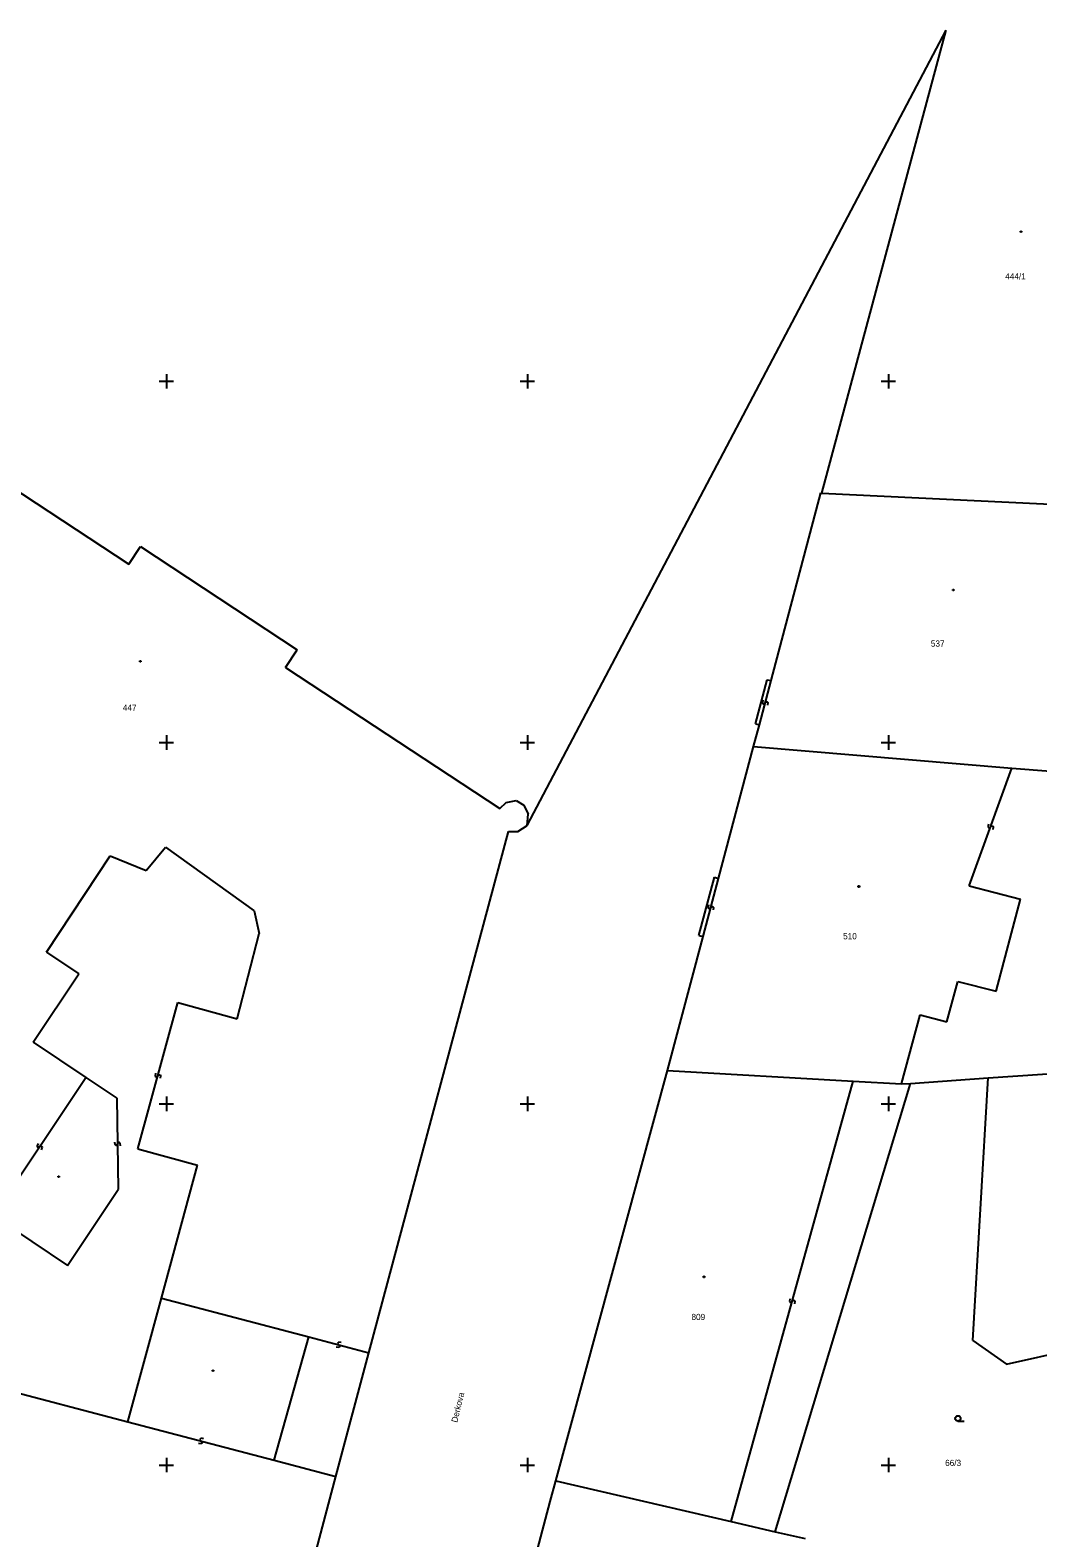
# Model space of a CAD drawing. Extents: x -492811 to -492366, y -1127107 to -1126748.
# Drawn here: x -492547.5 to -492491.7, y -1126844 to -1126760.6 of the extents above; entities that cross this region are included whole.
import ezdxf

# ---------------------------------------------------------------- set-up
doc = ezdxf.new("R2010")
doc.units = 0
doc.layers.add('katastrální mapa', color=7, linetype='Continuous')
doc.layers.add('síť', color=7, linetype='Continuous')

msp = doc.modelspace()

# ---------------------------------------------------------------- linework, layer by layer
at = {"layer": 'katastrální mapa'}
for p, q in [((-492520.02, -1126804.6), (-492496.81, -1126760.56)), ((-492503.68, -1126786.2), (-492496.81, -1126760.56)), ((-492492.68, -1126771.68), (-492492.62, -1126771.68)), ((-492492.68, -1126771.74), (-492492.68, -1126771.68)), ((-492492.62, -1126771.74), (-492492.68, -1126771.74)), ((-492492.62, -1126771.68), (-492492.62, -1126771.74)), ((-492554.24, -1126782.12), (-492542.08, -1126790.12)), ((-492506.5, -1126796.57), (-492503.75, -1126786.18)), ((-492503.75, -1126786.18), (-492503.68, -1126786.2)), ((-492503.68, -1126786.2), (-492489.88, -1126786.86)), ((-492542.08, -1126790.12), (-492541.44, -1126789.14)), ((-492541.44, -1126789.14), (-492532.75, -1126794.86)), ((-492496.43, -1126791.53), (-492496.37, -1126791.53)), ((-492496.43, -1126791.59), (-492496.43, -1126791.53)), ((-492496.37, -1126791.53), (-492496.37, -1126791.59)), ((-492496.37, -1126791.59), (-492496.43, -1126791.59)), ((-492533.4, -1126795.84), (-492532.75, -1126794.86)), ((-492541.47, -1126795.47), (-492541.41, -1126795.47)), ((-492541.47, -1126795.53), (-492541.47, -1126795.47)), ((-492541.41, -1126795.53), (-492541.47, -1126795.53)), ((-492541.41, -1126795.47), (-492541.41, -1126795.53)), ((-492533.4, -1126795.84), (-492521.53, -1126803.65)), ((-492507.36, -1126798.97), (-492506.71, -1126796.52)), ((-492507.15, -1126799.02), (-492506.5, -1126796.57)), ((-492506.71, -1126796.52), (-492506.5, -1126796.57)), ((-492506.95, -1126797.66), (-492506.97, -1126797.8)), ((-492506.97, -1126797.8), (-492506.94, -1126797.85)), ((-492506.94, -1126797.85), (-492506.9, -1126797.86)), ((-492506.9, -1126797.86), (-492506.85, -1126797.83)), ((-492506.85, -1126797.83), (-492506.8, -1126797.76)), ((-492506.8, -1126797.76), (-492506.75, -1126797.73)), ((-492506.75, -1126797.73), (-492506.71, -1126797.74)), ((-492506.71, -1126797.74), (-492506.68, -1126797.79)), ((-492506.68, -1126797.79), (-492506.7, -1126797.93)), ((-492507.47, -1126800.22), (-492507.15, -1126799.02)), ((-492507.36, -1126798.97), (-492507.15, -1126799.02)), ((-492509.41, -1126807.52), (-492507.47, -1126800.22)), ((-492507.47, -1126800.22), (-492493.16, -1126801.41)), ((-492495.52, -1126807.93), (-492493.16, -1126801.41)), ((-492493.16, -1126801.41), (-492491.03, -1126801.59)), ((-492521.17, -1126803.31), (-492520.62, -1126803.21)), ((-492520.62, -1126803.21), (-492520.2, -1126803.47)), ((-492521.53, -1126803.65), (-492521.17, -1126803.31)), ((-492520.2, -1126803.47), (-492519.95, -1126803.97)), ((-492520.02, -1126804.6), (-492519.95, -1126803.97)), ((-492528.79, -1126833.78), (-492521.05, -1126804.92)), ((-492521.05, -1126804.92), (-492520.53, -1126804.93)), ((-492520.53, -1126804.93), (-492520.02, -1126804.6)), ((-492494.46, -1126804.52), (-492494.49, -1126804.66)), ((-492494.49, -1126804.66), (-492494.46, -1126804.71)), ((-492494.46, -1126804.71), (-492494.42, -1126804.72)), ((-492494.42, -1126804.72), (-492494.37, -1126804.7)), ((-492494.37, -1126804.7), (-492494.31, -1126804.64)), ((-492494.31, -1126804.64), (-492494.26, -1126804.62)), ((-492494.26, -1126804.62), (-492494.22, -1126804.63)), ((-492494.22, -1126804.63), (-492494.19, -1126804.68)), ((-492494.19, -1126804.68), (-492494.22, -1126804.82)), ((-492546.63, -1126811.61), (-492543.11, -1126806.27)), ((-492543.11, -1126806.27), (-492541.12, -1126807.09)), ((-492541.12, -1126807.09), (-492540.04, -1126805.79)), ((-492540.04, -1126805.79), (-492535.14, -1126809.32)), ((-492510.5, -1126810.68), (-492509.64, -1126807.45)), ((-492510.26, -1126810.74), (-492509.41, -1126807.52)), ((-492509.64, -1126807.45), (-492509.41, -1126807.52)), ((-492501.67, -1126807.94), (-492501.61, -1126807.94)), ((-492501.67, -1126808), (-492501.67, -1126807.94)), ((-492501.61, -1126808), (-492501.67, -1126808)), ((-492501.61, -1126807.94), (-492501.61, -1126808)), ((-492495.52, -1126807.93), (-492492.69, -1126808.68)), ((-492509.96, -1126808.99), (-492509.98, -1126809.13)), ((-492509.86, -1126809.16), (-492509.81, -1126809.1)), ((-492509.81, -1126809.1), (-492509.76, -1126809.07)), ((-492509.76, -1126809.07), (-492509.72, -1126809.08)), ((-492509.72, -1126809.08), (-492509.69, -1126809.13)), ((-492494.04, -1126813.77), (-492492.69, -1126808.68)), ((-492535.14, -1126809.32), (-492534.86, -1126810.58)), ((-492509.98, -1126809.13), (-492509.95, -1126809.18)), ((-492509.95, -1126809.18), (-492509.91, -1126809.19)), ((-492509.91, -1126809.19), (-492509.86, -1126809.16)), ((-492509.69, -1126809.13), (-492509.71, -1126809.27)), ((-492536.07, -1126815.29), (-492534.86, -1126810.58)), ((-492512.23, -1126818.16), (-492510.26, -1126810.74)), ((-492510.5, -1126810.68), (-492510.26, -1126810.74)), ((-492546.63, -1126811.61), (-492544.85, -1126812.8)), ((-492547.38, -1126816.59), (-492544.85, -1126812.8)), ((-492496.77, -1126815.47), (-492496.15, -1126813.22)), ((-492496.15, -1126813.22), (-492494.04, -1126813.77)), ((-492541.58, -1126822.5), (-492539.36, -1126814.4)), ((-492539.36, -1126814.4), (-492536.07, -1126815.29)), ((-492499.28, -1126818.9), (-492498.24, -1126815.07)), ((-492498.24, -1126815.07), (-492496.77, -1126815.47)), ((-492547.38, -1126816.59), (-492544.46, -1126818.54)), ((-492518.43, -1126840.88), (-492512.23, -1126818.16)), ((-492512.23, -1126818.16), (-492501.96, -1126818.75)), ((-492494.47, -1126818.57), (-492484.66, -1126817.9)), ((-492549.58, -1126826.2), (-492544.46, -1126818.54)), ((-492544.46, -1126818.54), (-492542.74, -1126819.69)), ((-492540.6, -1126818.31), (-492540.62, -1126818.45)), ((-492540.62, -1126818.45), (-492540.59, -1126818.5)), ((-492540.59, -1126818.5), (-492540.55, -1126818.51)), ((-492540.55, -1126818.51), (-492540.5, -1126818.48)), ((-492540.5, -1126818.48), (-492540.44, -1126818.42)), ((-492540.44, -1126818.42), (-492540.39, -1126818.39)), ((-492540.39, -1126818.39), (-492540.35, -1126818.4)), ((-492540.35, -1126818.4), (-492540.32, -1126818.45)), ((-492540.32, -1126818.45), (-492540.34, -1126818.59)), ((-492508.71, -1126843.12), (-492501.96, -1126818.75)), ((-492506.28, -1126843.69), (-492498.78, -1126818.87)), ((-492501.96, -1126818.75), (-492499.28, -1126818.9)), ((-492499.28, -1126818.9), (-492498.78, -1126818.87)), ((-492498.78, -1126818.87), (-492494.47, -1126818.57)), ((-492495.32, -1126833.11), (-492494.47, -1126818.57)), ((-492542.74, -1126819.69), (-492542.66, -1126824.75)), ((-492547.1, -1126822.2), (-492547.16, -1126822.33)), ((-492547.16, -1126822.33), (-492547.15, -1126822.38)), ((-492547.15, -1126822.38), (-492547.11, -1126822.4)), ((-492547.11, -1126822.4), (-492547.06, -1126822.39)), ((-492547.06, -1126822.39), (-492546.98, -1126822.35)), ((-492546.98, -1126822.35), (-492546.93, -1126822.34)), ((-492546.88, -1126822.41), (-492546.94, -1126822.54)), ((-492546.93, -1126822.34), (-492546.89, -1126822.36)), ((-492546.89, -1126822.36), (-492546.88, -1126822.41)), ((-492542.84, -1126822.26), (-492542.86, -1126822.12)), ((-492542.8, -1126822.3), (-492542.84, -1126822.26)), ((-492542.76, -1126822.3), (-492542.8, -1126822.3)), ((-492542.72, -1126822.26), (-492542.76, -1126822.3)), ((-492542.68, -1126822.18), (-492542.72, -1126822.26)), ((-492542.64, -1126822.14), (-492542.68, -1126822.18)), ((-492542.6, -1126822.14), (-492542.64, -1126822.14)), ((-492542.56, -1126822.18), (-492542.6, -1126822.14)), ((-492542.54, -1126822.32), (-492542.56, -1126822.18)), ((-492541.58, -1126822.5), (-492538.27, -1126823.4)), ((-492546, -1126824), (-492545.94, -1126824)), ((-492546, -1126824.06), (-492546, -1126824)), ((-492545.94, -1126824.06), (-492546, -1126824.06)), ((-492545.94, -1126824), (-492545.94, -1126824.06)), ((-492540.27, -1126830.76), (-492538.27, -1126823.4)), ((-492545.47, -1126828.95), (-492542.66, -1126824.75)), ((-492549.58, -1126826.2), (-492545.47, -1126828.95)), ((-492510.25, -1126829.55), (-492510.19, -1126829.55)), ((-492510.25, -1126829.61), (-492510.25, -1126829.55)), ((-492510.19, -1126829.61), (-492510.25, -1126829.61)), ((-492510.19, -1126829.55), (-492510.19, -1126829.61)), ((-492542.13, -1126837.61), (-492540.27, -1126830.76)), ((-492540.27, -1126830.76), (-492532.11, -1126832.91)), ((-492505.46, -1126830.8), (-492505.48, -1126830.94)), ((-492505.48, -1126830.94), (-492505.45, -1126830.99)), ((-492505.45, -1126830.99), (-492505.41, -1126831)), ((-492505.41, -1126831), (-492505.36, -1126830.97)), ((-492505.36, -1126830.97), (-492505.31, -1126830.9)), ((-492505.31, -1126830.9), (-492505.26, -1126830.87)), ((-492505.26, -1126830.87), (-492505.22, -1126830.88)), ((-492505.22, -1126830.88), (-492505.19, -1126830.93)), ((-492505.19, -1126830.93), (-492505.21, -1126831.07)), ((-492493.46, -1126834.41), (-492482.75, -1126832.01)), ((-492534.03, -1126839.73), (-492532.11, -1126832.91)), ((-492532.11, -1126832.91), (-492528.79, -1126833.78)), ((-492530.5, -1126833.23), (-492530.51, -1126833.27)), ((-492530.51, -1126833.27), (-492530.48, -1126833.32)), ((-492530.45, -1126833.2), (-492530.5, -1126833.23)), ((-492530.31, -1126833.22), (-492530.45, -1126833.2)), ((-492495.32, -1126833.11), (-492493.46, -1126834.41)), ((-492530.61, -1126840.63), (-492528.79, -1126833.78)), ((-492530.45, -1126833.49), (-492530.59, -1126833.47)), ((-492530.48, -1126833.32), (-492530.42, -1126833.37)), ((-492530.4, -1126833.46), (-492530.45, -1126833.49)), ((-492530.42, -1126833.37), (-492530.39, -1126833.42)), ((-492530.39, -1126833.42), (-492530.4, -1126833.46)), ((-492553.93, -1126834.52), (-492542.13, -1126837.61)), ((-492537.45, -1126834.74), (-492537.39, -1126834.74)), ((-492537.45, -1126834.8), (-492537.45, -1126834.74)), ((-492537.39, -1126834.8), (-492537.45, -1126834.8)), ((-492537.39, -1126834.74), (-492537.39, -1126834.8)), ((-492542.13, -1126837.61), (-492534.03, -1126839.73)), ((-492496.15, -1126837.57), (-492495.8, -1126837.57)), ((-492538.08, -1126838.82), (-492538.22, -1126838.8)), ((-492538.13, -1126838.55), (-492538.14, -1126838.59)), ((-492538.14, -1126838.59), (-492538.11, -1126838.64)), ((-492538.08, -1126838.52), (-492538.13, -1126838.55)), ((-492538.11, -1126838.64), (-492538.05, -1126838.7)), ((-492537.94, -1126838.54), (-492538.08, -1126838.52)), ((-492538.03, -1126838.79), (-492538.08, -1126838.82)), ((-492538.05, -1126838.7), (-492538.02, -1126838.75)), ((-492538.02, -1126838.75), (-492538.03, -1126838.79)), ((-492534.03, -1126839.73), (-492530.61, -1126840.63)), ((-492535.01, -1126857.16), (-492530.61, -1126840.63)), ((-492518.73, -1126842.01), (-492518.43, -1126840.88)), ((-492518.43, -1126840.88), (-492508.71, -1126843.12)), ((-492521.03, -1126850.61), (-492518.73, -1126842.01)), ((-492508.71, -1126843.12), (-492506.28, -1126843.69)), ((-492506.28, -1126843.69), (-492504.62, -1126844.07))]:
    msp.add_line(p, q, dxfattribs=at)
msp.add_circle((-492496.15, -1126837.42), 0.15, dxfattribs=at)
at = {"layer": 'síť'}
for p, q in [((-492540, -1126779.6), (-492540, -1126780.4)), ((-492520, -1126779.6), (-492520, -1126780.4)), ((-492500, -1126779.6), (-492500, -1126780.4)), ((-492540.4, -1126780), (-492539.6, -1126780)), ((-492520.4, -1126780), (-492519.6, -1126780)), ((-492500.4, -1126780), (-492499.6, -1126780)), ((-492540, -1126799.6), (-492540, -1126800.4)), ((-492520, -1126799.6), (-492520, -1126800.4)), ((-492500, -1126799.6), (-492500, -1126800.4)), ((-492540.4, -1126800), (-492539.6, -1126800)), ((-492520.4, -1126800), (-492519.6, -1126800)), ((-492500.4, -1126800), (-492499.6, -1126800)), ((-492540, -1126819.6), (-492540, -1126820.4)), ((-492520, -1126819.6), (-492520, -1126820.4)), ((-492500, -1126819.6), (-492500, -1126820.4)), ((-492540.4, -1126820), (-492539.6, -1126820)), ((-492520.4, -1126820), (-492519.6, -1126820)), ((-492500.4, -1126820), (-492499.6, -1126820)), ((-492540, -1126839.6), (-492540, -1126840.4)), ((-492520, -1126839.6), (-492520, -1126840.4)), ((-492500, -1126839.6), (-492500, -1126840.4)), ((-492540.4, -1126840), (-492539.6, -1126840)), ((-492520.4, -1126840), (-492519.6, -1126840)), ((-492500.4, -1126840), (-492499.6, -1126840))]:
    msp.add_line(p, q, dxfattribs=at)

# ---------------------------------------------------------------- texts
at = {"layer": 'katastrální mapa'}
for s, p in [('444/1', (-492493.53, -1126774.36)), ('537', (-492497.65, -1126794.69)), ('447', (-492542.41, -1126798.24)), ('510', (-492502.51, -1126810.89)), ('809', (-492510.91, -1126831.97)), ('66/3', (-492496.86, -1126840.05))]:
    msp.add_text(s, height=0.34, dxfattribs=at).set_placement(p)
msp.add_text('Derkova', height=0.34, rotation=76.3371, dxfattribs=at).set_placement((-492523.89, -1126837.67))

doc.saveas('drawing.dxf')
